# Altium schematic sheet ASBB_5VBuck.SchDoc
size A4
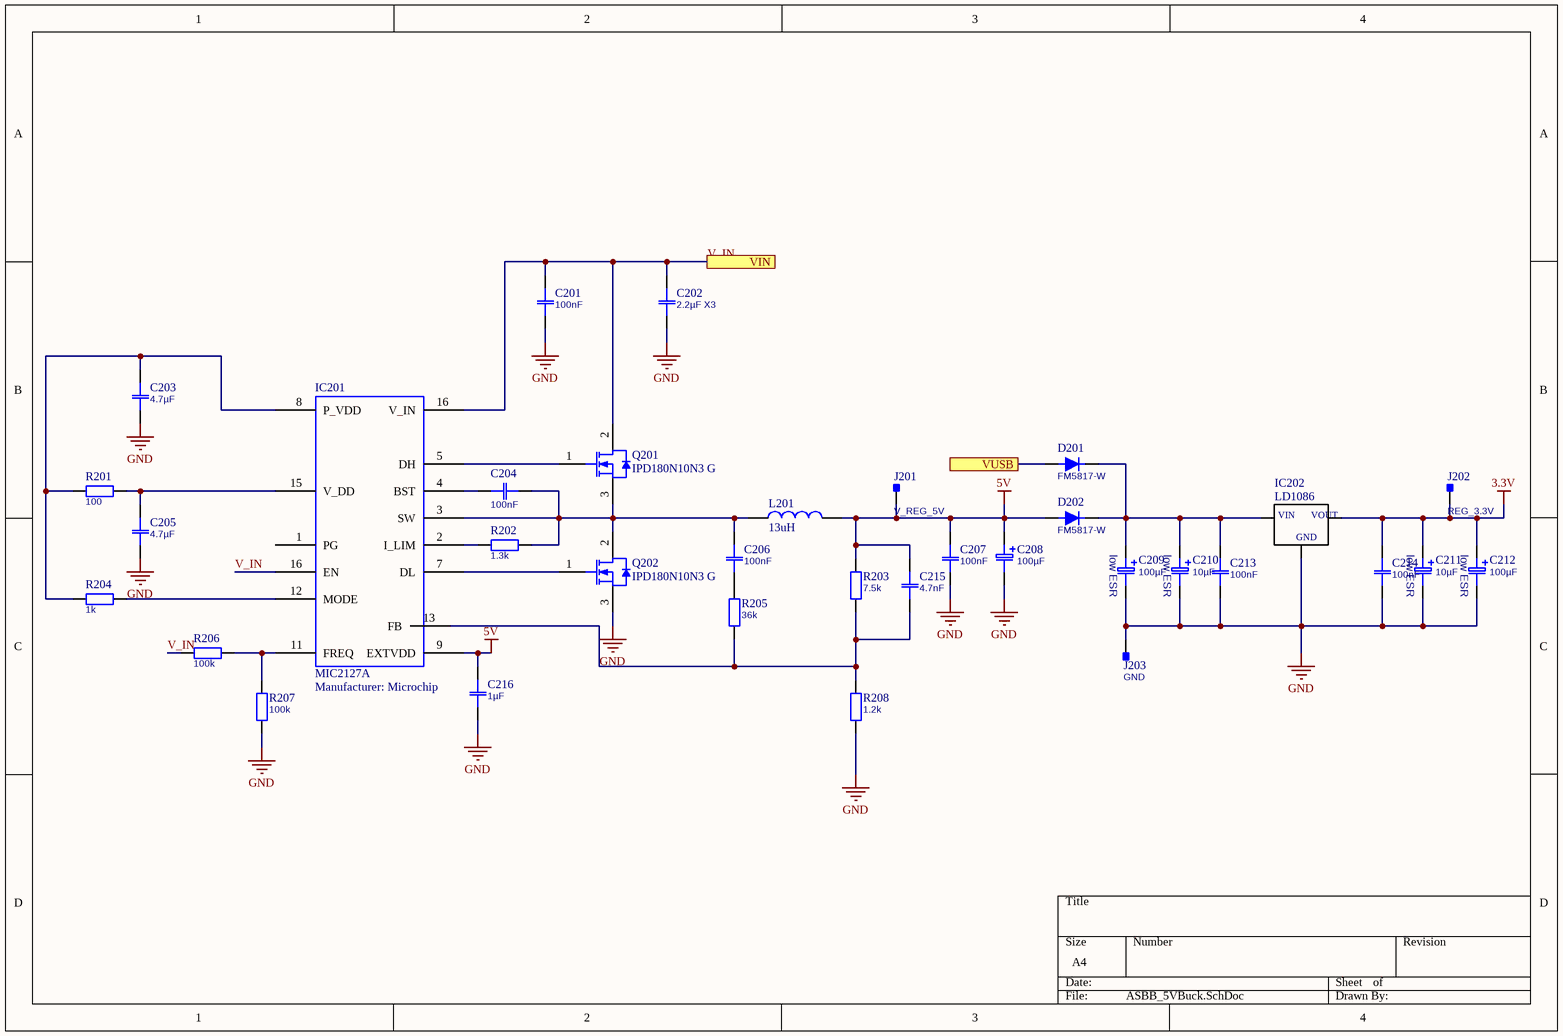
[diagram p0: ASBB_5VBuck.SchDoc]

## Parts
C201  100nF  [CAP 1206/3216]
C202  2.2µF X3  [CAP 1206/3216]
C203  4.7µF  [CAP 1206/3216]
C204  100nF  [CAP 1206/3216]
C205  4.7µF  [CAP 1206/3216]
C206  100nF  [0603]
C207  100nF  [0603]
C208  100µF  [CAP ALUM 6.6MM]
C209  100µF  [CAP ALUM 6.6MM]
C210  10µF  [CAP ALUM 6.6MM]
C211  10µF  [CAP ALUM 6.6MM]
C212  100µF  [CAP ALUM 6.6MM]
C213  100nF  [0603]
C214  100nF  [0603]
C215  4.7nF  [0603]
C216  1µF  [0603]
D201  FM5817-W  [SMB]
D202  FM5817-W  [SMB]
IC201  MIC2127A  Manufacturer: Microchip  [MCHP-QFN-MG16_N]
IC202  LD1086  [D2PAK_LD1086(Primary)]
J201  V_REG_5V  [PIN1]
J202  REG_3.3V  [PIN1]
J203  GND  [PIN1]
L201  value 13uH  [WE-HCI_1365_WE-PERM]  (hidden comment: 7443551131)
Q201  IPD180N10N3 G  [INF-PG-TO252-3-11_A_N]
Q202  IPD180N10N3 G  [INF-PG-TO252-3-11_A_N]
R201  100  [0603]
R202  1.3k  [0603]
R203  7.5k  [0603]
R204  1k  [0603]
R205  36k  [0603]
R206  100k  [CAP 1206/3216]
R207  100k  [CAP 1206/3216]
R208  1.2k  [0603]

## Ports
VIN, VUSB

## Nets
3.3V: C211.1(+) C212.1(+) C214.2 IC202.VOUT J202.1
5V: C207.1 C208.1(+) C215.1 C216.1 D202.2(A) IC201.9(EXTVDD) J201.1 L201.2 R203.2
GND: C201.1 C202.1 C203.2 C205.2 C207.2 C208.2(-) C209.2(-) C210.2(-) C211.2(-) C212.2(-) C213.1 C214.1 C216.2 IC202.GND J203.1 Q202.3(SOURCE) R207.1 R208.1
V_IN: C201.2 C202.2 IC201.16(EN) Q201.2(DRAIN) R206.1 ; port VIN
VUSB: D201.2(A) ; port VUSB
NetC203_1: C203.1 IC201.8(P_VDD) R201.1 R204.1
NetC204_1: C204.1 C206.1 IC201.3(SW) L201.1 Q201.3(SOURCE) Q202.2(DRAIN) R202.2
NetC204_2: C204.2 IC201.4(BST)
NetC205_1: C205.1 IC201.15(V_DD) R201.2
NetC206_2: C206.2 R205.2
NetC209_1: C209.1(+) C210.1(+) C213.2 D201.1(C) D202.1(C) IC202.VIN
NetC215_2: C215.2 IC201.13(FB) R203.1 R205.1 R208.2
NetIC201_2: IC201.2(I_LIM) R202.1
NetIC201_5: IC201.5(DH) Q201.1(GATE)
NetIC201_7: IC201.7(DL) Q202.1(GATE)
NetIC201_11: IC201.11(FREQ) R206.2 R207.2
NetIC201_12: IC201.12(MODE) R204.2

Not connected (* = marked no-connect by the designer): IC201 1(PG)

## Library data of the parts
C201-C207 C213-C216 = Capacitor
C208 = Capacitor polarised: Capacitor, polarised
C209-C212 = Capacitor polarised low ESR: Capacitor, polarised, low ESR
D201 D202 = Diode
IC201 = MIC2127A: 75V, Synchronous Buck Controller Featuring ADaptive On-Time Control
IC202 = LD1086: Semiconductors and Actives; MF: STMicroelectronics
J201-J203 = Pad 1 Pin: Pad, 1 Pin
L201 = 7443551131: WE-HCI SMD Flat Wire High Current Inductor, size 1365, 10A, 13uH; Material: WE-PERM
Q201 Q202 = IPD180N10N3 G: N-Channel OptiMOS 3 Power-Transistor, 100 V VDS, 43 A ID, -55 to 175 degC, PG-TO252-3-11, Reel, Green; Manufacturer: Infineon; Green: TRUE; ID (max): 43 A; IDpuls (max): 172 A; Polarity: N; Ptot (max): 71 W; QG: 19 nC; RDS (on) (max): 18 mOhm; Rth: 2.1 K/W; RthJA (max): 75 K/W; VDS (max): 100 V; VGS(th) (max): 3.5 V; VGS(th) (min): 2 V
R201-R208 = Resistor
